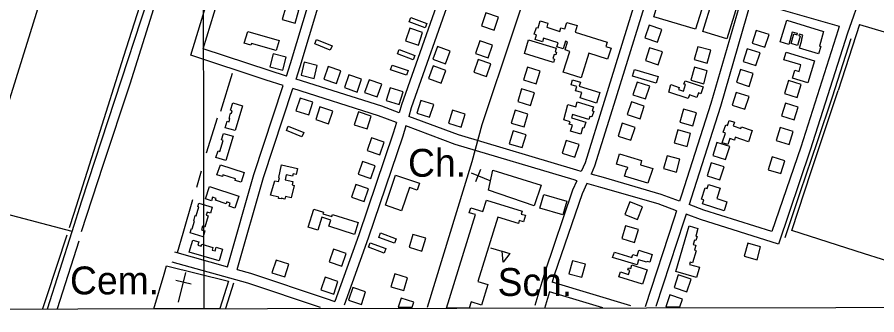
# Model space of a CAD drawing. Extents: x 3324125 to 3362000, y 600753 to 626151.
# Drawn here: x 3338211 to 3340770, y 606134 to 607022 of the extents above; entities that cross this region are included whole.
import ezdxf

# ---------------------------------------------------------------- set-up
doc = ezdxf.new("R2010")
doc.units = 0
for name, color, linetype in [('V-BLDG-IDEN', 7, 'Continuous'), ('V-BLDG-OTLN', 7, 'Continuous'), ('V-DTCH-CNTR', 7, 'Continuous'), ('V-GRID-FRAM', 7, 'Continuous'), ('V-GRID-MAJR', 7, 'Continuous'), ('V-ROAD-CNTR', 7, 'Continuous'), ('V-SITE-OTLN', 7, 'Continuous'), ('V-SITE-OTLN-IDEN', 7, 'Continuous'), ('V-TOPO-SHOR', 7, 'Continuous')]:
    doc.layers.add(name, color=color, linetype=linetype)

msp = doc.modelspace()

# ---------------------------------------------------------------- linework, layer by layer
at = {"layer": 'V-BLDG-OTLN'}
for p, q in [((3339597.3, 606442.3), (3339607.8, 606476.4)), ((3339607.8, 606476.4), (3339714.1, 606443.6)), ((3339556.9, 606439), (3339561.2, 606453.1)), ((3339575, 606433.4), (3339556.9, 606439)), ((3339561.2, 606453.1), (3339597.3, 606442.3)), ((3339714.1, 606443.6), (3339711.4, 606435)), ((3339711.4, 606435), (3339724, 606431.1)), ((3339488.9, 606154.1), (3339575, 606433.4)), ((3339641.4, 606425.7), (3339582.3, 606234.3)), ((3339703.1, 606407), (3339641.4, 606425.7)), ((3339705.8, 606415.6), (3339703.1, 606407)), ((3339718.1, 606411.8), (3339705.8, 606415.6)), ((3339724, 606431.1), (3339718.1, 606411.8)), ((3339619.8, 606334.2), (3339677.3, 606317.3)), ((3339582.3, 606234.3), (3339612.2, 606225)), ((3339612.2, 606225), (3339593.3, 606163.5)), ((3339344.7, 606157), (3339386.9, 606157)), ((3339557, 606154.3), (3339488.9, 606154.1)), ((3339562.7, 606172.9), (3339557, 606154.3)), ((3339593.3, 606163.5), (3339562.7, 606172.9)), ((3340141.9, 606158.4), (3340184, 606158.4))]:
    msp.add_line(p, q, dxfattribs=at)
for points in [[(3340106, 607022.9), (3340135.2, 607119.2), (3340259.8, 607081.5), (3340230.9, 606986.2)], [(3340252.3, 606978.8), (3340280.9, 607072.4), (3340318.8, 607060.8), (3340324.7, 607080.1), (3340358, 607069.9), (3340323.6, 606957.2)], [(3339038.4, 607004), (3339049, 607042.6), (3339010.4, 607053.1), (3338999.9, 607014.6)], [(3339630.9, 606983.5), (3339643.7, 607021.4), (3339605.8, 607034.3), (3339593, 606996.4)], [(3339425.2, 606990.2), (3339378.3, 607007.5), (3339383.1, 607020.6), (3339430.1, 607003.4)], [(3339967.1, 606947.2), (3339963.8, 606933.9), (3339979.1, 606929), (3339968.9, 606896.7), (3339912.8, 606914.5), (3339889.6, 606841.3), (3339836.5, 606858.1), (3339856.1, 606919.8), (3339842.2, 606924.2), (3339849.7, 606948), (3339843.4, 606950), (3339836.4, 606927.7), (3339817.5, 606933.7), (3339821.2, 606945.3), (3339778.1, 606959), (3339774.7, 606948.2), (3339752.6, 606955.2), (3339756.9, 606968.8), (3339750.2, 606971), (3339756.6, 606991.4), (3339761.5, 606989.8), (3339768.2, 607010.9), (3339791.2, 607003.6), (3339787.4, 606991.8), (3339826.4, 606979.4), (3339829.8, 606990.2), (3339840.9, 606986.6), (3339847.1, 607006.2), (3339877.7, 606996.6), (3339871.7, 606977.4)], [(3340092, 606998), (3340079.5, 606960), (3340117.5, 606947.5), (3340130, 606985.5)], [(3340539.9, 606929.2), (3340547.1, 606952.8), (3340545.6, 606953.2), (3340549.8, 606968.1), (3340539, 606971.1), (3340537.8, 606966.7), (3340542.1, 606965.5), (3340534.2, 606937.6), (3340515.1, 606943), (3340523.2, 606971.9), (3340532.7, 606969.2), (3340533.8, 606973.1), (3340518.7, 606977.4), (3340508.2, 606940.5), (3340482.4, 606947.8), (3340502.4, 607013.1), (3340612, 606979.4), (3340599.5, 606935.6), (3340603.2, 606934.5), (3340597.1, 606913)], [(3338897.3, 606979.5), (3338990.6, 606952.5), (3338981.9, 606922.4), (3338908.3, 606943.6), (3338906.7, 606938.1), (3338886.3, 606944)], [(3339405.5, 606938.4), (3339417.9, 606976.4), (3339379.8, 606988.8), (3339367.4, 606950.8)], [(3340411.2, 606982.2), (3340399, 606944.1), (3340437.1, 606931.9), (3340449.3, 606970)], [(3339102.3, 606955.6), (3339148.4, 606936.2), (3339143, 606923.3), (3339096.9, 606942.7)], [(3339613.1, 606900.3), (3339625.9, 606938.2), (3339588, 606951), (3339575.2, 606913.1)], [(3339720.9, 606913.1), (3339732.9, 606954.1), (3339815.5, 606929.2), (3339812.3, 606918.5), (3339816.9, 606917.1), (3339814.4, 606909.1), (3339809.5, 606910.6), (3339805.8, 606898.2), (3339810.4, 606896.8), (3339807.4, 606887.1)], [(3339390.2, 606894.8), (3339343.4, 606912.3), (3339348.2, 606925.4), (3339395.1, 606907.9)], [(3339462.1, 606934.1), (3339448.7, 606896.4), (3339486.4, 606883), (3339499.8, 606920.7)], [(3340093.9, 606930.5), (3340081.4, 606892.5), (3340119.4, 606880), (3340131.9, 606918)], [(3340265.4, 606884.5), (3340276.1, 606923), (3340237.5, 606933.7), (3340226.8, 606895.2)], [(3340384.5, 606927.7), (3340372.4, 606889.6), (3340410.5, 606877.4), (3340422.6, 606915.5)], [(3339001.8, 606863.7), (3339011.5, 606902.6), (3338972.7, 606912.3), (3338963, 606873.5)], [(3339608.5, 606845.1), (3339621.3, 606883), (3339583.4, 606895.8), (3339570.6, 606857.9)], [(3340500.8, 606917), (3340584.7, 606891.7), (3340565, 606825.9), (3340519.3, 606839.6), (3340526.6, 606863.6), (3340538.6, 606860), (3340544.5, 606879.6), (3340493.7, 606894.9)], [(3339065.5, 606887.5), (3339056, 606848.7), (3339094.8, 606839.1), (3339104.4, 606878)], [(3339123.6, 606837.2), (3339161.4, 606824), (3339174.6, 606861.8), (3339136.9, 606875)], [(3339370.1, 606849.4), (3339322.6, 606865.2), (3339327, 606878.5), (3339374.5, 606862.7)], [(3339448.9, 606876.3), (3339435.6, 606838.6), (3339473.3, 606825.2), (3339486.6, 606862.9)], [(3339729.8, 606872.9), (3339718.2, 606834.6), (3339756.4, 606822.9), (3339768.1, 606861.2)], [(3340254.9, 606823.3), (3340265.6, 606861.9), (3340227.1, 606872.6), (3340216.3, 606834)], [(3339185.2, 606812), (3339223, 606798.7), (3339236.2, 606836.5), (3339198.4, 606849.7)], [(3340042.4, 606845.8), (3340048.6, 606865.6), (3340118.9, 606844.7), (3340112.9, 606824.8)], [(3340364.4, 606865.8), (3340352.3, 606827.7), (3340390.4, 606815.5), (3340402.5, 606853.6)], [(3339245.1, 606797.4), (3339282.9, 606784.1), (3339296.1, 606821.9), (3339258.3, 606835.1)], [(3339945.4, 606797.3), (3339935.6, 606765.9), (3339887.1, 606781), (3339892, 606796.9), (3339873.3, 606802.7), (3339877.2, 606815.1), (3339859.9, 606820.5), (3339864.3, 606834.9), (3339887.8, 606827.6), (3339884.3, 606816.3)], [(3340056.4, 606828.5), (3340043.9, 606790.5), (3340081.9, 606778), (3340094.4, 606816)], [(3340150.9, 606798.4), (3340157.2, 606820.8), (3340181.4, 606812.6), (3340179.4, 606806.6), (3340194.3, 606801.5), (3340200.7, 606820.6), (3340196, 606822.2), (3340199.5, 606832.5), (3340253.6, 606814.3), (3340246.6, 606793.6), (3340239.3, 606796.1), (3340234.8, 606782.6), (3340212.1, 606790.2), (3340208.3, 606779)], [(3340533.4, 606782.5), (3340545.2, 606820.7), (3340507, 606832.6), (3340495.2, 606794.4)], [(3339347.8, 606761.5), (3339359.7, 606799.7), (3339321.5, 606811.5), (3339309.6, 606773.3)], [(3339712.8, 606808.3), (3339701.1, 606770), (3339739.4, 606758.4), (3339751, 606796.6)], [(3340351.8, 606797.5), (3340339.6, 606759.4), (3340377.7, 606747.2), (3340389.9, 606785.3)], [(3339091.3, 606768.2), (3339053.4, 606780.8), (3339040.7, 606742.9), (3339078.7, 606730.2)], [(3339400.7, 606735.5), (3339438.8, 606723.3), (3339451, 606761.4), (3339412.9, 606773.6)], [(3339850.1, 606761.9), (3339874, 606754.7), (3339878.5, 606769.5), (3339926.6, 606755), (3339922.9, 606742.9), (3339927.4, 606741.6), (3339922.2, 606724.3), (3339915.9, 606726.2), (3339913.1, 606717), (3339864.5, 606731.7), (3339861.4, 606721.5), (3339903.7, 606708.7), (3339898.4, 606691), (3339894.3, 606692.3), (3339888.6, 606673.3), (3339858.6, 606682.4), (3339863.9, 606699.7), (3339854.7, 606702.5), (3339856.9, 606709.8), (3339838, 606715.5)], [(3340039.8, 606769.4), (3340027.3, 606731.4), (3340065.3, 606718.9), (3340077.8, 606756.9)], [(3338830.5, 606692.2), (3338836.3, 606711.4), (3338841.5, 606709.8), (3338844.3, 606719.3), (3338841.5, 606720.1), (3338846.2, 606736.1), (3338848.9, 606735.3), (3338851.2, 606743), (3338846.2, 606744.5), (3338852.6, 606766), (3338881.9, 606757.4), (3338860.1, 606683.5)], [(3339150.2, 606741.8), (3339112.3, 606754.4), (3339099.6, 606716.5), (3339137.6, 606703.8)], [(3339494.6, 606706.3), (3339532.7, 606694.1), (3339545, 606732.2), (3339506.9, 606744.4)], [(3339693.4, 606744.6), (3339681.7, 606706.3), (3339720, 606694.7), (3339731.6, 606732.9)], [(3340222.4, 606698), (3340233.1, 606736.6), (3340194.6, 606747.3), (3340183.9, 606708.8)], [(3340524.4, 606715.6), (3340536.3, 606753.8), (3340498, 606765.6), (3340486.2, 606727.4)], [(3339265.1, 606726.6), (3339227.1, 606739.2), (3339214.5, 606701.3), (3339252.4, 606688.7)], [(3339017.8, 606697.2), (3339064, 606678), (3339058.6, 606665.1), (3339012.4, 606684.2)], [(3340012.3, 606705.5), (3339999.8, 606667.5), (3340037.8, 606655), (3340050.3, 606693)], [(3340399.6, 606683.8), (3340388.5, 606650.5), (3340349, 606663.8), (3340346.2, 606655.6), (3340332.6, 606660.2), (3340326.4, 606641.8), (3340309.6, 606647.4), (3340319.4, 606676.5), (3340313.1, 606678.6), (3340320.6, 606700.7), (3340325.7, 606699), (3340330.8, 606714.2), (3340346.8, 606708.8), (3340343, 606697.6), (3340365.5, 606690), (3340367.1, 606694.7)], [(3340509.2, 606642.7), (3340521, 606680.9), (3340482.8, 606692.7), (3340471, 606654.5)], [(3338831.7, 606594.9), (3338802.7, 606603.5), (3338808.8, 606623.1), (3338813.7, 606621.6), (3338823.8, 606654.2), (3338819, 606655.7), (3338825.2, 606675.5), (3338853.9, 606666.6)], [(3339687.7, 606682.8), (3339676, 606644.6), (3339714.3, 606632.9), (3339725.9, 606671.2)], [(3340205.3, 606636.4), (3340216, 606674.9), (3340177.4, 606685.6), (3340166.7, 606647.1)], [(3339290.5, 606611.2), (3339303.4, 606649), (3339265.5, 606661.9), (3339252.6, 606624)], [(3339871.6, 606604), (3339883.8, 606642.1), (3339845.7, 606654.3), (3339833.5, 606616.2)], [(3340294.1, 606648), (3340281.9, 606609.9), (3340320, 606597.7), (3340332.2, 606635.8)], [(3340088.8, 606526.5), (3340019.1, 606548.1), (3340025.8, 606569.6), (3340027.8, 606569), (3340029.1, 606573.4), (3339994.9, 606584), (3340004.4, 606614.5), (3340070, 606594.1), (3340066.3, 606582.1), (3340103, 606570.7)], [(3339263.7, 606541), (3339276.5, 606578.8), (3339238.7, 606591.7), (3339225.8, 606553.8)], [(3340173.4, 606559.6), (3340184.1, 606598.1), (3340145.6, 606608.8), (3340134.9, 606570.3)], [(3340484.8, 606555.3), (3340496.7, 606593.5), (3340458.5, 606605.3), (3340446.6, 606567.1)], [(3338815.7, 606581.3), (3338886.6, 606559.2), (3338877.4, 606529.9), (3338859.8, 606535.4), (3338861.3, 606540.3), (3338823.4, 606552.1), (3338821.8, 606546.9), (3338805.3, 606552.1)], [(3338965.2, 606491), (3338977.7, 606534.3), (3338989.2, 606531.7), (3338991.8, 606543.1), (3338989.4, 606543.6), (3338998.2, 606581.9), (3339045.7, 606571), (3339041.6, 606553.1), (3339032.3, 606555.2), (3339030.6, 606547.9), (3339011.9, 606552.2), (3339008.5, 606537.3), (3339031.6, 606532), (3339029.2, 606521.6), (3339035.5, 606520.2), (3339027, 606483.2), (3339009.9, 606487.1), (3339008.1, 606479.4), (3338996.8, 606482), (3338996.3, 606479.9), (3338988.6, 606481.6), (3338989.5, 606485.4)], [(3339613.9, 606506.1), (3339627.2, 606565.6), (3339771, 606521.2), (3339749.8, 606459.4)], [(3340277.2, 606587.4), (3340265, 606549.3), (3340303.1, 606537.1), (3340315.3, 606575.2)], [(3339307.9, 606460.9), (3339337.5, 606550.5), (3339408.7, 606527), (3339402, 606506.6), (3339378.4, 606514.4), (3339355.4, 606444.9)], [(3338771.1, 606479.8), (3338783.8, 606517.3), (3338870.6, 606488), (3338858.6, 606452.4), (3338842.1, 606458), (3338845.3, 606467.6), (3338835, 606471.1), (3338833, 606465.3), (3338801.5, 606475.9), (3338803.4, 606481.5), (3338792.7, 606485.1), (3338788.9, 606474)], [(3339244, 606472.6), (3339256.8, 606510.5), (3339219, 606523.3), (3339206.1, 606485.5)], [(3340251.5, 606465.7), (3340255, 606477), (3340248.3, 606479.1), (3340258.9, 606512.9), (3340265.3, 606510.9), (3340269.2, 606523.3), (3340304.1, 606512.3), (3340294.2, 606480.8), (3340324.2, 606471.3), (3340315.9, 606444.9)], [(3339778.8, 606493.3), (3339846.9, 606473.5), (3339835.1, 606433), (3339767, 606452.9)], [(3338764.2, 606366.5), (3338725.9, 606379.2), (3338729.8, 606391.9), (3338732, 606391.2), (3338738.9, 606413.9), (3338736.4, 606414.7), (3338741.2, 606430.5), (3338743.4, 606429.8), (3338751.6, 606456.9), (3338748.8, 606457.7), (3338751.7, 606467.1), (3338791.4, 606455.1), (3338786, 606437.2), (3338776, 606440.3), (3338773.2, 606431.2), (3338779.9, 606429.2), (3338769.8, 606396.2), (3338762.4, 606398.5), (3338759.3, 606388.1), (3338769.8, 606384.9)], [(3340072.4, 606456.2), (3340035.3, 606471.1), (3340020.4, 606434), (3340057.5, 606419.1)], [(3339225.6, 606409.9), (3339214.8, 606374.2), (3339138.6, 606398.3), (3339144.5, 606417.1), (3339117.8, 606425.5), (3339105.7, 606386.9), (3339077, 606395.9), (3339093.8, 606449.2), (3339122.4, 606440.2), (3339121, 606435.5), (3339147.3, 606427.2), (3339149.5, 606433.9)], [(3340049, 606350.2), (3340060.7, 606388.4), (3340022.5, 606400.2), (3340010.7, 606361.9)], [(3340211.2, 606399.6), (3340237.5, 606391.7), (3340231, 606369.3), (3340235.1, 606368), (3340231.6, 606355.8), (3340227, 606357.1), (3340223.3, 606344.6), (3340231.7, 606342.2), (3340227.2, 606326.9), (3340232.4, 606325.4), (3340221.8, 606289.3), (3340214.8, 606291.3), (3340212.9, 606285), (3340242.7, 606276.3), (3340233.7, 606245.7), (3340171.4, 606264)], [(3339292.1, 606378.6), (3339339, 606361.5), (3339334.3, 606348.3), (3339287.3, 606365.4)], [(3339415.7, 606324.4), (3339427.3, 606362.7), (3339389.1, 606374.3), (3339377.4, 606336)], [(3338723.3, 606321.3), (3338733.5, 606356.9), (3338751.5, 606351.6), (3338748.7, 606342), (3338758.7, 606339), (3338760.4, 606344.7), (3338793.6, 606334.9), (3338791.5, 606327.7), (3338800.4, 606325), (3338803.7, 606336.1), (3338822.4, 606330.6), (3338811.9, 606295.1)], [(3339261.7, 606349.4), (3339308.5, 606331.8), (3339303.6, 606318.7), (3339256.8, 606336.3)], [(3340424.4, 606337.3), (3340385.8, 606347.7), (3340375.4, 606309), (3340414, 606298.6)], [(3339177.2, 606279.2), (3339190.1, 606317), (3339152.2, 606329.9), (3339139.4, 606292)], [(3339677.3, 606317.3), (3339657.8, 606291.7), (3339655.2, 606323.8)], [(3339983.7, 606305.7), (3339989.4, 606321.5), (3340040.9, 606305.8), (3340043.6, 606314.7), (3340056.7, 606310.7), (3340061.7, 606327.1), (3340101.8, 606314.8), (3340094.5, 606291), (3340086.7, 606293.3), (3340086, 606291.1), (3340061, 606298.7), (3340056.4, 606283.5)], [(3338969.4, 606259.6), (3339007.5, 606247.3), (3339019.8, 606285.3), (3338981.8, 606297.7)], [(3339863.8, 606295.6), (3339853.7, 606257), (3339892.3, 606246.8), (3339902.5, 606285.5)], [(3340002.5, 606248), (3340007.6, 606262.4), (3340031.2, 606255), (3340035, 606267), (3340029.3, 606268.8), (3340031.1, 606274.6), (3340037.7, 606272.6), (3340041.1, 606283.2), (3340086.3, 606269), (3340072.8, 606226)], [(3339361.6, 606206.7), (3339373.2, 606245), (3339334.9, 606256.6), (3339323.3, 606218.4)], [(3339115.1, 606208.6), (3339153.1, 606196.3), (3339165.4, 606234.3), (3339127.4, 606246.7)], [(3340179.3, 606253.4), (3340166.7, 606215.5), (3340204.7, 606202.9), (3340217.2, 606240.9)], [(3339197.7, 606177.9), (3339235.7, 606165.3), (3339248.2, 606203.3), (3339210.2, 606215.8)]]:
    msp.add_lwpolyline(points, close=True, dxfattribs=at)
for points in [[(3339386.9, 606157), (3339391.8, 606171.9), (3339353.8, 606184.5), (3339344.7, 606157)], [(3340153.7, 606194), (3340141.9, 606158.4)], [(3340184, 606158.4), (3340191.6, 606181.4), (3340153.7, 606194)]]:
    msp.add_lwpolyline(points, dxfattribs=at)
at = {"layer": 'V-DTCH-CNTR'}
msp.add_line((3340719.1, 607000.2), (3340655.3, 606803), dxfattribs=at)
for points in [[(3338300.8, 606152.1), (3338374.2, 606382.7), (3338403.2, 606474), (3338501.1, 606774.2), (3338599.8, 607075.2), (3338701.1, 607390.7), (3338775.2, 607618.8), (3338744.7, 607628.7), (3338527.3, 607698.8), (3338341.3, 607755.8), (3338223, 607376.8), (3338458.8, 607309.6)], [(3340719.1, 607000.2), (3340939.5, 606934.7), (3341098.1, 606883.6), (3341150.4, 606865.7), (3341069.6, 606616.2), (3340993.8, 606383), (3340982.7, 606383.8), (3340935.9, 606252.6), (3340733.5, 606316.4), (3340517.4, 606386.2), (3340575.3, 606562), (3340655.3, 606803)], [(3338374.2, 606382.7), (3338159.8, 606439.6), (3337996.9, 606486.4), (3337887, 606513.4)]]:
    msp.add_lwpolyline(points, dxfattribs=at)
at = {"layer": 'V-GRID-FRAM'}
msp.add_lwpolyline([(3328210, 624318.2), (3328233.8, 606134.5), (3359834, 606189.7), (3359794.3, 624373.3), (3328210, 624318.2)], dxfattribs=at)
at = {"layer": 'V-GRID-MAJR'}
msp.add_spline([(3338767.2, 606152.9), (3338757.5, 612211), (3338747.8, 618272.2), (3338738.1, 624333.5), (3338738.1, 624336.6)], degree=3, dxfattribs=at)
at = {"layer": 'V-ROAD-CNTR'}
for points in [[(3339432.1, 606157.1), (3339565.6, 606591.7), (3339595.2, 606701.5), (3339779.9, 607255.8), (3339850.8, 607457.2), (3339938.7, 607750.4), (3339991.4, 607937.6), (3340033.3, 608065.6), (3340109.3, 608306.5), (3340151.5, 608473.1)], [(3339003, 606817.7), (3338951.8, 606833.9), (3338727.7, 606908.5), (3338930.1, 607573.7), (3339207.5, 607493)], [(3339012.4, 606846.2), (3338961.1, 606862.5), (3338764.9, 606927.8), (3338950.2, 607536.6), (3339199.2, 607464.2)], [(3339012.4, 606846.2), (3339024.8, 606883.7), (3339197.5, 607458.3), (3339199.2, 607464.2)], [(3339041, 606837.1), (3339053.4, 606874.7), (3339226.3, 607449.8), (3339228.1, 607456.1)], [(3339560.7, 607362), (3339477.5, 607107.9), (3339355.5, 606760.6), (3339348.3, 606736.8)], [(3339589.5, 607353.3), (3339505.9, 607098.2), (3339384.1, 606751.3), (3339376.5, 606726.2)], [(3340784.5, 607265.8), (3340768.3, 607217.6), (3340683.2, 606974.6), (3340572.3, 606625.3), (3340477.1, 606345), (3340245.4, 606418.3), (3340202.5, 606434.2)], [(3340080.7, 607165.5), (3339958.3, 606770.6), (3339901.9, 606588), (3339890.1, 606562)], [(3340109.3, 607156.3), (3339987, 606761.7), (3339930, 606577.3), (3339919.4, 606553.8)], [(3340366.5, 607075.9), (3340275.9, 606764.1), (3340188.7, 606491.2), (3340183.2, 606473.4)], [(3340395.5, 607068.1), (3340304.6, 606755.4), (3340217.3, 606482.2), (3340211.3, 606462.9)], [(3340395.5, 607068.1), (3340477.7, 607046.2), (3340658.5, 606994.6)], [(3340658.5, 606994.6), (3340654.8, 606984.1), (3340543.8, 606634.7), (3340458.2, 606382.4), (3340255.2, 606446.7), (3340211.3, 606462.9)], [(3339348.3, 606736.8), (3339296.4, 606756.2), (3339041, 606837.1)], [(3338836.8, 606277.4), (3338915.4, 606552.7), (3339003, 606817.7)], [(3338865.7, 606269.3), (3338944.1, 606543.9), (3339031.6, 606808.7)], [(3339339.7, 606708), (3339286.6, 606727.8), (3339031.6, 606808.7)], [(3339890.1, 606562), (3339877.3, 606565.6), (3339524.3, 606670.9), (3339376.5, 606726.2)], [(3339339.7, 606708), (3339330, 606675.8), (3339227.8, 606373.2), (3339156.4, 606174.5)], [(3339367.8, 606697.4), (3339358.6, 606666.7), (3339256.1, 606363.3), (3339184.1, 606162.9)], [(3339877.6, 606534.3), (3339868.9, 606536.8), (3339514.7, 606642.4), (3339367.8, 606697.4)], [(3340183.2, 606473.4), (3340128.5, 606493.6), (3339956.7, 606543.4), (3339919.4, 606553.8)], [(3339877.6, 606534.3), (3339864.6, 606505.9), (3339781.5, 606261.6), (3339752.4, 606161.9)], [(3339906.8, 606526.2), (3339892.6, 606494.8), (3339810.1, 606252.5), (3339804.1, 606232.1)], [(3340174.3, 606444.7), (3340119.1, 606465.1), (3339948.5, 606514.5), (3339906.8, 606526.2)], [(3340174.3, 606444.7), (3340167.4, 606422.4), (3340080.4, 606158.2)], [(3340202.5, 606434.2), (3340196, 606413.3), (3340112.5, 606159.7)], [(3338679.1, 606321.8), (3338836.8, 606277.4)], [(3338671, 606292.9), (3338896.5, 606229.5), (3339112.7, 606157.4)], [(3338865.7, 606269.3), (3338905.3, 606258.2), (3339131.2, 606182.8), (3339156.4, 606174.5)], [(3340038.2, 606161), (3339804.1, 606232.1)], [(3339795.7, 606203.3), (3339781.2, 606153.5)], [(3339954.4, 606155.1), (3339795.7, 606203.3)]]:
    msp.add_lwpolyline(points, dxfattribs=at)
at = {"layer": 'V-SITE-OTLN'}
for p, q in [((3339589.8, 606567.7), (3339574.9, 606530.6)), ((3339619.5, 606534.3), (3339563.8, 606556.6)), ((3338617.4, 606152.6), (3338648.4, 606255.6)), ((3338648.4, 606255.6), (3338655.3, 606280.5)), ((3338655.3, 606280.5), (3338839.8, 606235.2)), ((3338691, 606172.2), (3338713.1, 606260.7)), ((3338728.6, 606225.5), (3338682.9, 606236.9)), ((3338839.8, 606235.2), (3338814.1, 606153)), ((3338814.1, 606153), (3338617.4, 606152.6))]:
    msp.add_line(p, q, dxfattribs=at)
at = {"layer": 'V-TOPO-SHOR'}
for p, q in [((3338817.3, 606741.3), (3338852, 606855.2)), ((3338774.8, 606617.7), (3338807.6, 606722)), ((3338745.8, 606515.4), (3338759.3, 606563.6))]:
    msp.add_line(p, q, dxfattribs=at)
for points in [[(3338944.7, 607569.8), (3338857, 607599), (3338799.3, 607617.5), (3338764.7, 607516.3), (3338713.4, 607358.7), (3338676.2, 607244.6), (3338612.1, 607030.8), (3338546, 606822.3), (3338465.5, 606579.9), (3338401.5, 606381.6)], [(3338727, 607535.9), (3338684.3, 607401.8), (3338615.9, 607182.1), (3338527.4, 606904.5), (3338451.3, 606662), (3338379.7, 606436.5), (3338365.9, 606394)], [(3338357.7, 607324.4), (3338249.6, 606974.9), (3338091.2, 606470.9)], [(3340497.3, 606365), (3340543.4, 606502.4), (3340594, 606651.3), (3340638.6, 606784.8), (3340693.7, 606958.2)], [(3338687.9, 606320.3), (3338705.3, 606378.3), (3338734.2, 606478.7)], [(3338358.2, 606371.8), (3338298.1, 606187.7), (3338286.6, 606152)], [(3338394.2, 606354.2), (3338338.1, 606177.5), (3338329.8, 606152.1)], [(3338855.3, 606228.4), (3338831.2, 606153)]]:
    msp.add_lwpolyline(points, dxfattribs=at)

# ---------------------------------------------------------------- texts
at = {"layer": 'V-BLDG-IDEN'}
msp.add_text('Sch.', height=83, dxfattribs=at).set_placement((3339641.2, 606190.8))
at = {"layer": 'V-SITE-OTLN-IDEN'}
for s, p in [('Ch.', (3339374.5, 606546.1)), ('Cem.', (3338368.1, 606195.5))]:
    msp.add_text(s, height=83, dxfattribs=at).set_placement(p)

doc.saveas('drawing.dxf')
